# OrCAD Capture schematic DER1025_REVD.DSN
size B; title: DER-1025 revC; rev: D
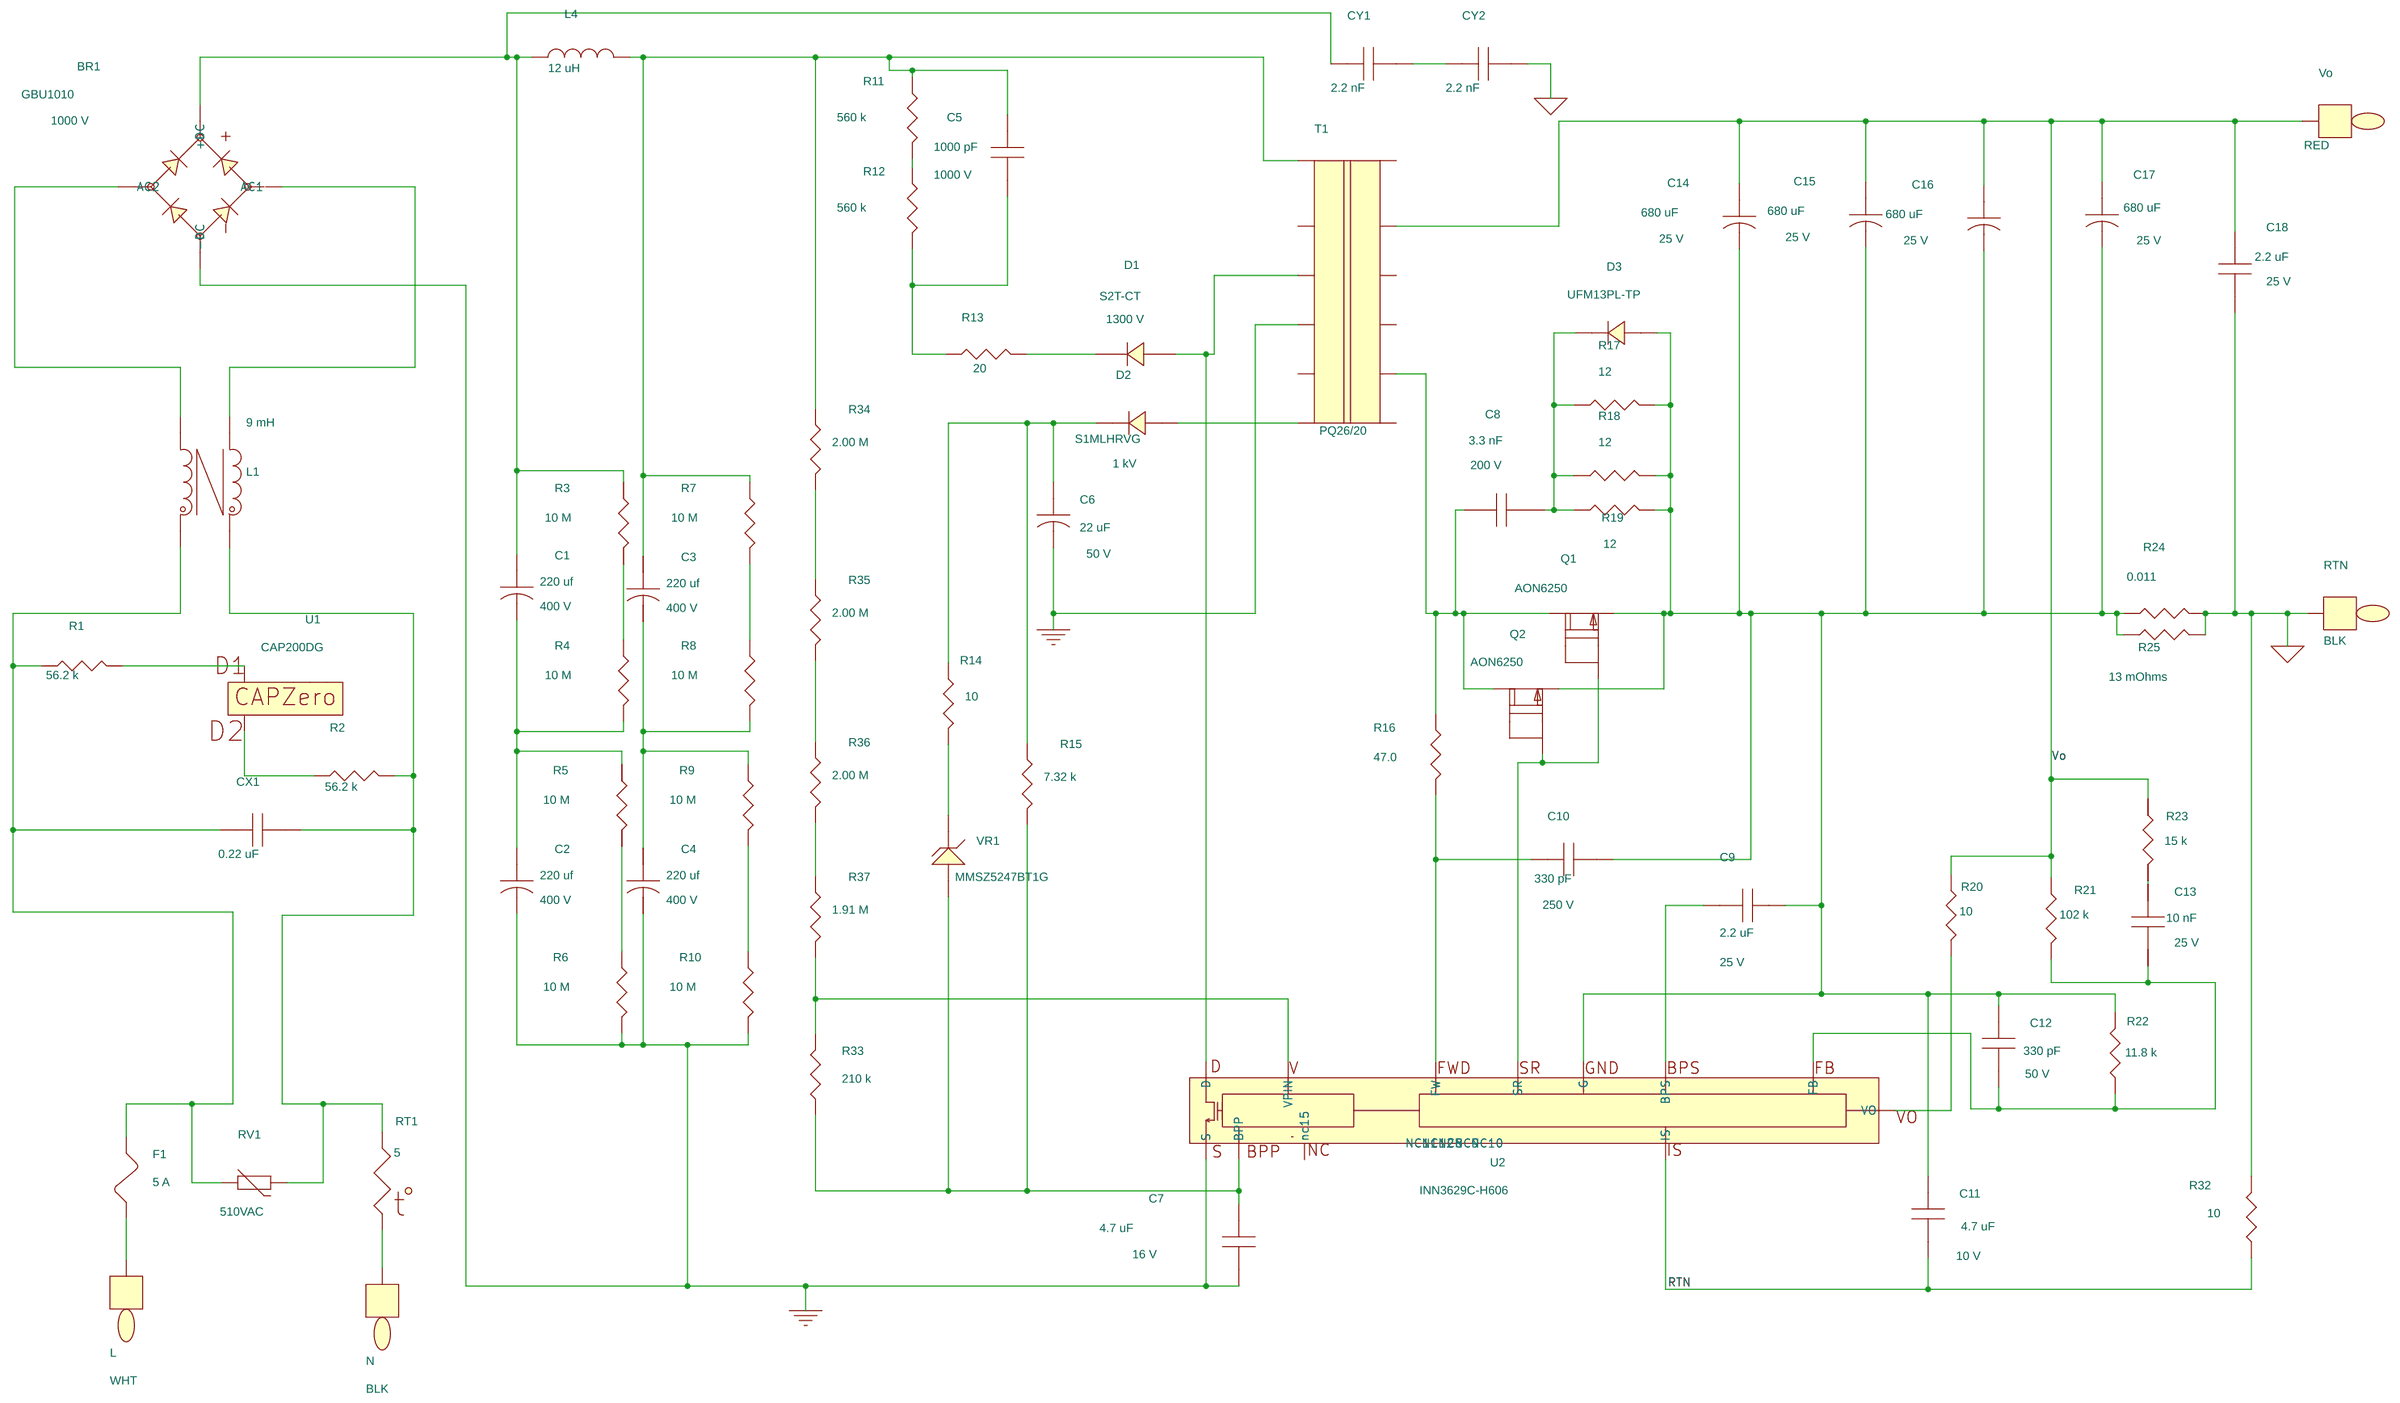
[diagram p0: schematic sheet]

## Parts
BR1  GBU1010  [pidaxbridgegbu8]
C1  220 uf  [pipolcapclyd710ls300040]
C2  220 uf  [pipolcapclyd710ls300040]
C3  220 uf  [pipolcapclyd710ls300040]
C4  220 uf  [pipolcapclyd710ls300040]
C5  1000 pF  [pismc1206]
C6  22 uF  [pipolcapclyd5mmd030]
C7  4.7 uF  [pismc0805]
C8  3.3 nF  [pismc0805]
C9  2.2 uF  [pismc0805]
C10  330 pF  [pismc0603]
C11  4.7 uF  [pismc0805]
C12  330 pF  [pismc0603]
C13  10 nF  [pismc0603]
C14  680 uF  [pipolcapcyld8mmd030]
C15  680 uF  [pipolcapcyld8mmd030]
C16  680 uF  [pipolcapcyld8mmd030]
C17  680 uF  [pipolcapcyld8mmd030]
C18  2.2 uF  [pismc0805]
CX1  0.22 uF  [pinpcaprad26x8p5x18d040]
CY1  2.2 nF  [pinpycaprad540x290ls400040]
CY2  2.2 nF  [pinpycaprad540x290ls400040]
D1  S2T-CT  [pismdo214aa12]
D2  S1MLHRVG  [pi_sm_sod-123_12]
D3  UFM13PL-TP  [pi_sm_sod-123_12]
F1  5 A  [pi_rst_microfuse]
L  WHT  [pitpkeystone125x125]
L1  9 mH  [pi4p19x10mmD046_12_43]
L4  12 uH  [pi_choke_coilcraft_rfb1010]
N  BLK  [pitpkeystone125x125]
Q1  AON6250  [pismpqfn5x6b]
Q2  AON6250  [pismpqfn5x6b]
R1  56.2 k  [pismr1206]
R2  56.2 k  [pismr1206]
R3  10 M  [pismr1206]
R4  10 M  [pismr1206]
R5  10 M  [pismr1206]
R6  10 M  [pismr1206]
R7  10 M  [pismr1206]
R8  10 M  [pismr1206]
R9  10 M  [pismr1206]
R10  10 M  [pismr1206]
R11  560 k  [pismr1206]
R12  560 k  [pismr1206]
R13  20  [pismr1210]
R14  10  [pismr0603]
R15  7.32 k  [pismr0805]
R16  47.0  [pismr1206]
R17  12  [pismr1206]
R18  12  [pismr1206]
R19  12  [pismr1206]
R20  10  [pismr0402]
R21  102 k  [pismr0603]
R22  11.8 k  [pismr0603]
R23  15 k  [pismr0603]
R24  0.011  [pismr1206]
R25  13 mOhms  [pismr1206]
R32  10  [pismr0805]
R33  210 k  [pismr0805]
R34  2.00 M  [pismr1206]
R35  2.00 M  [pismr1206]
R36  2.00 M  [pismr1206]
R37  1.91 M  [pismr1206]
RT1  5  [pi_rad770x220ls330d052]
RTN  BLK  [pitpkeystone125x125]
RV1  510VAC  [pi_disc1100x290ls400x220d040]
T1  PQ26/20  [pi_bobbin_bpq26_20_12p_2]
U1  CAP200DG  [pi_ic_smd_so8_capzero]
U2  INN3629C-H606  [pi_ic_insop_24d]
Vo  RED  [pitpkeystone125x125]
VR1  MMSZ5247BT1G  [pi_sm_sod-123_12]

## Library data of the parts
BR1 = DISCRETE_BRIDGE_+~~-: Disp_Voltage: 1000 V; Part Number: 15-01985-00
C1-C4 = CAP_POL: ALT_SYMBOLS: pi_cap_cly_d710_ls300_040_1000h,pipolcapd710ls3000401600lhoriz; Disp_Voltage: 400 V; FPLIST: pipolcapclyd710ls300040,pi_cap_cly_d710_ls300_040_1000h,pipolcapd710ls3000401600lhoriz; Part Number: 20-01926-00; Voltage: 400 V
C5 = CAP_NP: Disp_Voltage: 1000 V; Part Number: 20-01391-00; Voltage: 1000 V
C6 = CAP_POL: ALT_SYMBOLS: pipolcapclyd5x11mmd030H; Disp_Voltage: 50 V; FPLIST: pipolcapclyd5mmd030,pipolcapclyd5x11mmd030H; Part Number: 20-02059-00; Voltage: 50 V
C7 = CAP_NP: ALT_SYMBOLS: Unisem_RMCF0805UL; Disp_Voltage: 16 V; Part Number: 20-09166-00; Voltage: 16 V
C8 = CAP_NP: ALT_SYMBOLS: Unisem_RMCF0805UL; Disp_Voltage: 200 V; FPLIST: pismc0805,Unisem_RMCF0805UL; Part Number: 20-00956-00; Voltage: 200 V
C9 = CAP_NP: ALT_SYMBOLS: Unisem_RMCF0805UL; Disp_Voltage: 25 V; Part Number: 20-01594-00; Voltage: 25 V
C10 = CAP_NP: ALT_SYMBOLS: Unisem_RMCF0603UL; Disp_Voltage: 250 V; FPLIST: pismc0603,Unisem_RMCF0603UL; Part Number: 20-01651-00; Voltage: 250 V
C11 = CAP_NP: ALT_SYMBOLS: Unisem_RMCF0805UL; Disp_Voltage: 10 V; Part Number: 20-01487-00; Voltage: 10 V
C12 = CAP_NP: ALT_SYMBOLS: Unisem_RMCF0603UL; Disp_Voltage: 50 V; Part Number: 20-08676-00; Voltage: 50 V
C13 = CAP_NP: ALT_SYMBOLS: Unisem_RMCF0603UL; Disp_Voltage: 25 V; FPLIST: pismc0603,Unisem_RMCF0603UL; Part Number: 20-09120-00; Voltage: 25 V
C14-C17 = CAP_POL: ALT_SYMBOLS: pipolcapcyld8x16mmd030H; Disp_Voltage: 25 V; FPLIST: pipolcapcyld8mmd030,pipolcapcyld8x16mmd030H; Part Number: 20-01579-00; Voltage: 25 V
C18 = CAP_NP: ALT_SYMBOLS: Unisem_RMCF0805UL; Disp_Voltage: 25 V; FPLIST: pismc0805,Unisem_RMCF0805UL; Part Number: 20-09264-00; Voltage: 25 V
CX1 = CAP_NP: ALT_SYMBOLS: pinpcaprad26x8p5x18d040H; Disp_Voltage: 480 VAC; FPLIST: pinpcaprad26x8p5x18d040,pinpcaprad26x8p5x18d040H; Part Number: 20-01879-00; Voltage: 480 VAC
CY1 CY2 = CAP_NP: Disp_Voltage: 760 VAC; Part Number: 20-01427-00; Voltage: 760 VAC
D1 = DIODE: Disp_Voltage: 1300 V; Part Number: 15-01834-00
D2 = DIODE: Disp_Voltage: 1 kV; Part Number: 15-01663-00
D3 = DIODE: Disp_Voltage: 200 V; Part Number: 15-01801-00
F1 = FUSE: ALT_SYMBOLS: pirstmicrofusehoz; FPLIST: pi_rst_microfuse,pirstmicrofusehoz; Part Number: 40-00052-00
L = TESTPOINT: ALT_SYMBOLS: TP_5010-14; FPLIST: pitpkeystone125x125,TP_5010-14; Part Number: 35-00044-00
L1 = TORRID_4P_12_43a: Part Number: 32-00457-00
L4 = INDUCTOR: Part Number: 30-00482-00
N RTN = TESTPOINT: Part Number: 35-00042-00
Q1 Q2 = FET_N_SGD_123_4_5678: Part Number: 50-00167-00
R1 R2 = R: Disp_Tol: 1%; Part Number: 05-00361-00
R3-R10 = R: Part Number: 05-01445-00
R11 R12 = R: Part Number: 05-01418-00
R13 = R: Disp_Power: 0.5 W; Part Number: 05-06460-00
R14 = R: ALT_SYMBOLS: Unisem_RMCF0603UL; Disp_Tol: 1%; Part Number: 05-00886-00
R15 = R: ALT_SYMBOLS: Unisem_RMCF0805UL; Disp_Tol: 1%; FPLIST: pismr0805,Unisem_RMCF0805UL; Part Number: 05-03389-00
R16 = R: Disp_Tol: 1%; Part Number: 05-03475-00
R17-R19 = R: Part Number: 05-01306-00
R20 = R: ALT_SYMBOLS: Unisem_RMCF0402UL,pismr0402_1; Disp_Tol: 1%; FPLIST: pismr0402,Unisem_RMCF0402UL,pismr0402_1; Part Number: 05-05596-00
R21 = R: ALT_SYMBOLS: Unisem_RMCF0603UL; Disp_Tol: 1%; FPLIST: pismr0603,Unisem_RMCF0603UL; Part Number: 05-01175-00
R22 = R: ALT_SYMBOLS: Unisem_RMCF0603UL; Disp_Tol: 1%; FPLIST: pismr0603,Unisem_RMCF0603UL; Part Number: 05-03189-00
R23 = R: ALT_SYMBOLS: Unisem_RMCF0603UL; Disp_Tol: 1%; FPLIST: pismr0603,Unisem_RMCF0603UL; Part Number: 05-03199-00
R24 = R: Disp_Power: 1 W; Disp_Tol: 1%; Part Number: 05-06466-00
R25 = R: Disp_Power: 1 W; Disp_Tol: 1%; Part Number: 05-07023-00
R32 = R: ALT_SYMBOLS: Unisem_RMCF0805UL; Disp_Tol: 1%; Part Number: 05-00492-00
R33 = R: ALT_SYMBOLS: Unisem_RMCF0805UL; Disp_Tol: 1%; FPLIST: pismr0805,Unisem_RMCF0805UL; Part Number: 05-00811-00
R34-R36 = R: Disp_Tol: 1%; Part Number: 05-03156-00
R37 = R: Disp_Tol: 1%; Part Number: 05-05409-00
RT1 = THERMISTOR: Part Number: 90-00032-00
RV1 = VARISTOR: Part Number: 85-00069-00
T1 = BPQ26_20_12P_GENERIC: Part Number: 25-01140-00
U1 = CAPZero: Part Number: 10-00958-00
U2 = Inno3EP_P15: Part Number: 10-01549-00
Vo = TESTPOINT: Part Number: 35-00043-00
VR1 = DIODE_ZENER: Part Number: 15-01362-00

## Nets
GND: BR1.4(-DC) C2.2 C4.2 C6.2 C7.2 R6.2 R10.2 T1.4 U2.16(S)
GND SIGNAL: C18.2 CY2.2 R24.2 R25.2 R32.1 RTN.1
NC8: U2.8(NC8)
NC9: U2.9(NC9)
NC10: U2.10(NC10)
NC11: U2.11(NC11)
NC12: U2.12(NC12)
RTN: C11.2 R32.2 U2.1(IS)
Vo: C14.1 C15.1 C16.1 C17.1 C18.1 R20.1 R21.1 R23.1 T1.11 Vo.1
N37461: C8.2 D3.1 R17.1 R18.1 R19.1
N37469: C9.1 C10.2 C11.1 C12.1 C14.2 C15.2 C16.2 C17.2 D3.2 Q1.1(S) Q2.1(S) R17.2 R18.2 R19.2 R22.2 R24.1 R25.1 U2.2(G)
N38055: C6.1 D2.1 R14.1 R15.1
N38189: C7.1 R15.2 R33.1 U2.14(BPP) VR1.2
N100542: D1.1 R13.2
N100730: C5.2 R12.2 R13.1
N100745: C3.1 C5.1 L4.2 R7.1 R11.1 R34.1 T1.1
N100844: R11.2 R12.1
N104424: C8.1 Q1.5(D) Q2.5(D) R16.1 T1.8
N108780: C12.2 C13.2 R21.2 R22.1 U2.3(FB)
N109833: C13.1 R23.2
N12293127: C10.1 R16.2 U2.7(FW)
N12305547: Q1.4(G) Q2.4(G) U2.5(SR)
N12342924: D1.2 T1.3 U2.24(D)
N12352620: C3.2 C4.1 R8.2 R9.1
N12353333: BR1.1(+DC) C1.1 CY1.1 L4.1 R3.1
N12359836: R7.2 R8.1
N12360252: R9.2 R10.1
N12374653: R3.2 R4.1
N12374691: C1.2 C2.1 R4.2 R5.1
N12374751: R5.2 R6.1
N12405316: BR1.3(AC2) L1.2
N12405324: BR1.2(AC1) L1.3
N12405376: CX1.1 F1.2 L1.1 R1.1 RV1.1
N12405380: CX1.2 L1.4 R2.2 RT1.1 RV1.2
N12407233: F1.1 L.1
N12407237: N.1 RT1.2
N12426226: R20.2 U2.6(VO)
N12433777: D2.2 T1.6
N12606053: R14.2 VR1.1
N13222962: R1.2 U1.2(D1)
N13223037: R2.1 U1.7(D2)
N13228168: R33.2 R37.2 U2.13(VPIN)
N13228288: R34.2 R35.1
N13228295: R35.2 R36.1
N13228312: R36.2 R37.1
N13231702: C9.2 U2.4(BPS)
N13238248: CY1.2 CY2.1

Not connected (* = marked no-connect by the designer): Q1 2(S2) 3(S3) 6(D6) 7(D7) 8(D8); Q2 2(S2) 3(S3) 6(D6) 7(D7) 8(D8); T1 2 5 7 9 10 12; U1 1(NC1) 3(NC2) 4(NC3) 5(NC4) 6(NC5) 8(NC8); U2 15(nc15)
